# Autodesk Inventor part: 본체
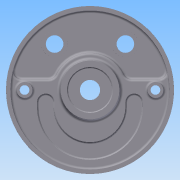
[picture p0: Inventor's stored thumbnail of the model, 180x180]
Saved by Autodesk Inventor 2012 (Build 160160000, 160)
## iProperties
Created: 2015-04
Part Number: 본체
Material: 알루미늄-6061
Document SubType Name: Modeling
Designer: net
Density: 2.71 g/cm^3
Mass: 1038.84 g
Surface Area: 1020.36 cm^2
Volume: 383.336 cm^3
Author: net
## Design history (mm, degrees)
sketch "스케치1"
  geometry: C1 r 95 at (0, 0); 1 further point
  constraints: 1 centre point, 1 coincident
  dimensions: "d0" = 190 diameter of C1
extrude "돌출1" new body sketch "스케치1" distance "d1" = 32; taper "d2" = 0 deg
feature "쉘1" dims "d3" = 5
feature "면 이동1"
sketch "스케치4"
  geometry: L1 (-76.916, 12)-(-47.117, 12); L2 (47.117, 12)-(76.916, 12); C1 r 25 at (0, 0) reference; C2 r 90 at (0, 0) reference; C3 r 90 at (0, 0) reference; A1 r 42 centre (0, 0) between (38.056, 17.769) and (-38.056, 17.769); A2 r 90 centre (0, 0) between (86.53, 24.75) and (-86.53, 24.75); A3 r 10 centre (-47.117, 22) between (-47.117, 12) and (-38.056, 17.769); A4 r 10 centre (-76.916, 22) between (-86.53, 24.75) and (-76.916, 12); A5 r 10 centre (47.117, 22) between (38.056, 17.769) and (47.117, 12); A6 r 10 centre (76.916, 22) between (76.916, 12) and (86.53, 24.75); 5 further points
  constraints: 16 point on circle, 8 tangent, 6 centre point, 4 end point, 4 point on line, 3 equal radius, 2 coincident, 2 horizontal, 1 collinear, 1 vertical alignment
  dimensions: "d10" = 84 diameter of A1; "d11" = 180 diameter of A2; "d13" = 12 distance from line of L2 C1.centre; "d14" = 10 radius of A3
extrude "돌출4" cut sketch "스케치4" distance "d15" = 7; taper "d16" = 0 deg
sketch "스케치5"
  geometry: L1 (-47.117, 12)-(-76.916, 12) reference; L2 (-59, -19)-(59, -19); L3 (-59, -14)-(59, -14); L4 (41, -19)-(41, -14); L5 (59, -19)-(59, -14); L6 (-59, -19)-(-59, -14); L7 (-41, -19)-(-41, -14); A1 r 90 centre (0, 0) between (-86.53, 24.75) and (86.53, 24.75) reference; A2 r 59 centre (0, -19) between (-59, -19) and (59, -19); A3 r 41 centre (0, -19) between (-41, -19) and (41, -19); A4 r 9 centre (-50, -14) between (-41, -14) and (-59, -14); A5 r 9 centre (50, -14) between (59, -14) and (41, -14); 2 further points
  constraints: 12 end point, 8 point on circle, 8 point on line, 4 centre point, 4 tangent, 3 parallel, 3 perpendicular, 2 coincident, 2 vertical alignment, 1 midpoint
  dimensions: "d17" = 19 distance from line of A1.centre L2; "d20" = 59 radius of A2; "d21" = 41 radius of A3; "d23" = 5 distance between parallel lines of L2 L3
extrude "돌출5" cut sketch "스케치5" distance "d24" = 7; taper "d25" = 0 deg
sketch "스케치6"
  geometry: C1 r 35 at (0, 0); A1 r 42 centre (0, 0) between (38.056, 17.769) and (-38.056, 17.769) reference
  constraints: 1 centre point, 1 coincident
  dimensions: "d26" = 70 diameter of C1
extrude "돌출6" join sketch "스케치6" distance "d27" = 10; taper "d28" = 0 deg
sketch "스케치7"
  geometry: C1 r 35 at (0, 0) reference; C2 r 25 at (0, 0)
  constraints: 1 centre point, 1 coincident
  dimensions: "d29" = 50 diameter of C2
extrude "돌출7" cut sketch "스케치7" distance "d30" = 15; taper "d31" = 0 deg
sketch "스케치8"
  geometry: C1 r 25 at (0, 0) reference; C2 r 11.5 at (0, 0)
  constraints: 1 centre point, 1 coincident
  dimensions: "d32" = 23 diameter of C2
extrude "돌출8" cut sketch "스케치8" stored distance "d33" = 15; taper "d34" = 0 deg
sketch "스케치9"
  geometry: L1 (0, 0)-(-94.638, -8.28); L2 (0, 0)-(94.638, -8.28); L3 (-47.117, 12)-(-76.916, 12) reference; L4 (76.916, 12)-(47.117, 12) reference; C1 r 90 at (0, 0) reference; C2 r 95 at (0, 0) reference; A1 r 95 centre (0, 0) between (-94.638, -8.28) and (94.638, -8.28); A2 r 90 centre (0, 0) between (-89.658, -7.844) and (89.658, -7.844); 1 further point
  constraints: 4 end point, 4 point on circle, 3 coincident, 2 centre point, 2 concentric, 2 point on line
  dimensions: "d35" = 5 deg angle of L3 L1; "d36" = 5 deg angle of L4 L2
extrude "돌출9" cut sketch "스케치9" distance "d37" = 5; taper "d38" = 0 deg
sketch "스케치10"
  geometry: C1 r 15 at (-40, 52); C2 r 15 at (40, 52); A1 r 42 centre (0, 0) between (38.056, 17.769) and (-38.056, 17.769) reference
  constraints: 2 centre point, 1 equal radius, 1 horizontal alignment
  dimensions: "d39" = 52 vertical distance of C2.centre A1.centre; "d40" = 80 distance of C1.centre C2.centre; "d41" = 40 horizontal distance of A1.centre C2.centre; "d42" = 30 diameter of C1
extrude "돌출10" join sketch "스케치10" stored distance "d43" = 5; taper "d44" = 0 deg
sketch "스케치11"
  geometry: C1 r 15 at (0, 0) reference; C2 r 15 at (80, 0) reference; C3 r 10 at (0, 0); C4 r 10 at (80, 0); 1 further point
  constraints: 2 centre point, 2 coincident, 1 equal radius
  dimensions: "d45" = 20 diameter of C4
extrude "돌출11" cut sketch "스케치11" stored distance "d46" = 5; taper "d47" = 0 deg
sketch "스케치12"
  geometry: L1 (-6, 13.748)-(-6, -13.748); L2 (6, 13.748)-(6, -13.748); C1 r 10 at (0, 0) reference; A1 r 15 centre (0, 0) between (-6, 13.748) and (6, 13.748) reference; 1 further point
  constraints: 4 end point, 4 point on circle, 2 vertical
  dimensions: "d48" = 12 distance between parallel lines of L2 L1; "d49" = 6 distance from line of C1.centre L1
extrude "돌출12" cut sketch "스케치12" distance "d50" = 3; taper "d51" = 0 deg
sketch "스케치13"
  geometry: L1 (-13.748, 6)-(13.748, 6); L2 (-13.748, -6)-(13.748, -6); C1 r 10 at (0, 0) reference; A1 r 15 centre (0, 0) between (13.748, -6) and (13.748, 6) reference; 1 further point
  constraints: 4 end point, 4 point on circle, 1 horizontal, 1 parallel
  dimensions: "d52" = 12 distance between parallel lines of L2 L1; "d53" = 6 distance from line of L1 C1.centre
extrude "돌출13" cut sketch "스케치13" distance "d54" = 3; taper "d55" = 0 deg
sketch "스케치15"
  geometry: C1 r 35 at (0, 0) reference; C2 r 9 at (-74, 0); C3 r 9 at (74, 0); A1 r 90 centre (0, 0) between (-86.53, 24.75) and (86.53, 24.75) reference
  constraints: 2 centre point, 2 horizontal alignment, 1 equal radius
  dimensions: "d58" = 148 distance of C2.centre C3.centre; "d59" = 74 distance of C1.centre C3.centre (= 0.5 x d58); "d60" = 18 diameter of C3
extrude "돌출14" join sketch "스케치15" stored distance "d61" = 3; taper "d62" = 0 deg
sketch "스케치14"
  geometry: C1 r 11.5 at (0, 0) reference; A1 r 41 centre (0, -19) between (-41, -19) and (41, -19) reference; 2 further points
  constraints: 2 horizontal alignment
  dimensions: "d56" = 148 distance of point (74, 0) point (-74, 0); "d70" = 74 distance of C1.centre point (-74, 0) (= 0.5 x d56)
hole "구멍1" sketch "스케치14" diameter "d63" = 11; stored, may be unused: countersink angle "d67" = 90 deg, drill point angle "d69" = 118 deg; dims "d64" = 6, "d65" = 18, "d66" = 11, "d68" = 8
sketch "스케치16"
  geometry: L1 (39.44, -39.44)-(47.244, -47.244); L2 (-39.44, -39.44)-(-47.244, -47.244); C1 r 11.5 at (0, 0) reference; C2 r 95 at (0, 0) reference; A1 r 51 centre (0, 0) between (-32.699, -39.138) and (32.699, -39.138); A2 r 72 centre (0, 0) between (-46.97, -54.569) and (46.97, -54.569); A3 r 5 centre (-35.904, -42.975) between (-32.699, -39.138) and (-39.44, -39.44); A4 r 5 centre (-43.709, -50.78) between (-47.244, -47.244) and (-46.97, -54.569); A5 r 5 centre (35.904, -42.975) between (39.44, -39.44) and (32.699, -39.138); A6 r 5 centre (43.709, -50.78) between (46.97, -54.569) and (47.244, -47.244); 5 further points
  constraints: 17 point on circle, 8 tangent, 6 centre point, 6 point on line, 4 end point, 3 equal radius, 2 coincident, 1 vertical alignment
  dimensions: "d71" = 51 radius of A1; "d72" = 72 radius of A2; "d73" = 90 deg angle of L1 L2; "d101" = 5 radius of A3
extrude "돌출15" join sketch "스케치16" distance "d74" = 5; taper "d75" = 0 deg
chamfer "모따기1" distance "d76" = 1; stored, may be unused: second distance "d77" = 2, angle "d78" = 45 deg
fillet "모깎기1" dims "d79" = 3
chamfer "모따기2" distance "d80" = 1; stored, may be unused: second distance "d81" = 2, angle "d82" = 45 deg
chamfer "모따기4" distance "d86" = 10; stored, may be unused: second distance "d87" = 2, angle "d88" = 10 deg
fillet "모깎기3" dims "d90" = 3
fillet "모깎기4" dims "d91" = 3
fillet "모깎기5" dims "d92" = 5
fillet "모깎기9" dims "d99" = 0.3
fillet "모깎기10" dims "d100" = 3
fillet "모깎기11" dims "d105" = 5
sketch "스케치19"
  geometry: C1 r 68 at (0, 0); A1 r 56 centre (0, 0) between (-35.904, -42.975) and (35.904, -42.975) reference
  constraints: 1 centre point, 1 coincident, 1 other
  dimensions: "d106" = 136 diameter of C1
feature "엠보싱3" sketch "스케치19" dims "d10" = 84, "d11" = 180, "d13" = 12, "d14" = 10, "d107" = 0.5, "d108" = 0
fillet "모깎기12" dims "d109" = 3
fillet "모깎기13" dims "d110" = 1
node "솔리드1"
other parameters: "d12" = 12
